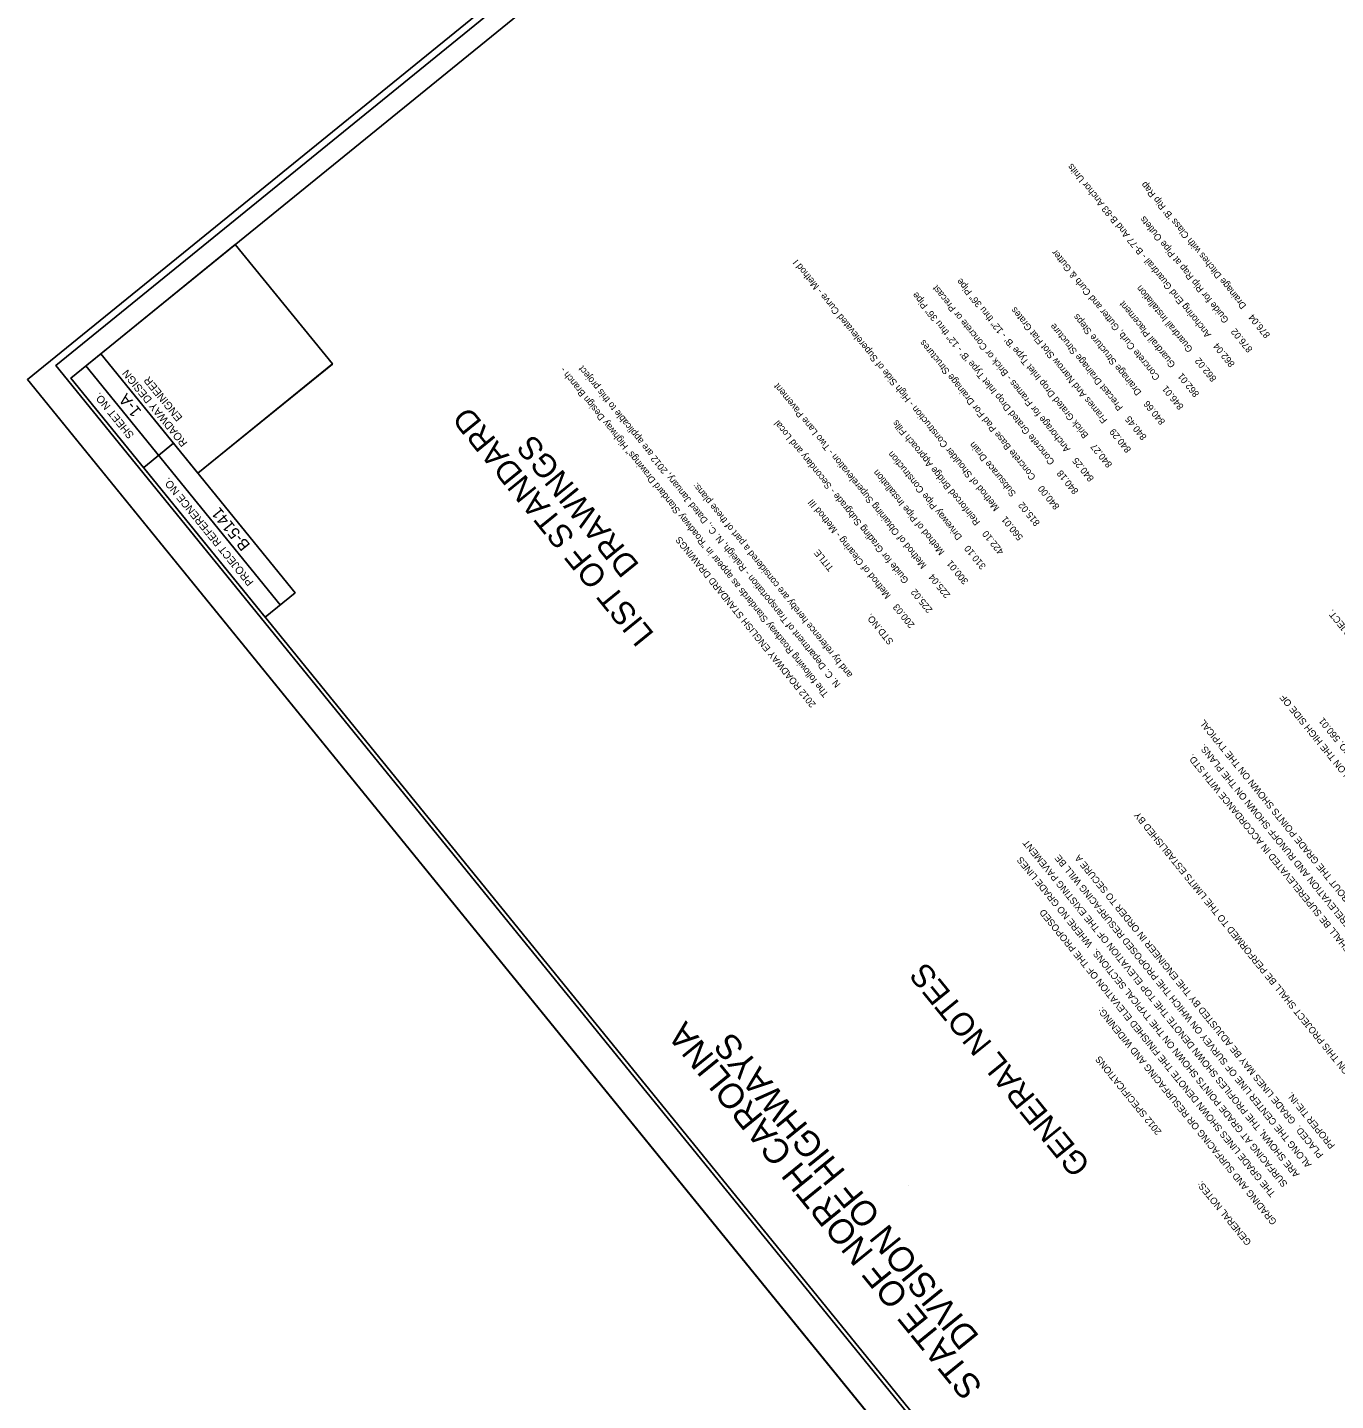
# Model space of a CAD drawing. Extents: x 2596486 to 2602076, y 851390 to 856110.
# Drawn here: x 2600164 to 2601014, y 853035 to 853927 of the extents above; entities that cross this region are included whole.
import ezdxf

# ---------------------------------------------------------------- set-up
doc = ezdxf.new("R2010")
doc.units = 0
for name, color, linetype in [('Sheet Cutting Line CELL', 7, 'Continuous'), ('Sheet Data Field CELL', 7, 'Continuous'), ('Sheet Data Text CELL', 7, 'Continuous'), ('Sheet Plan CELL', 7, 'Continuous'), ('Sheet Plot Border Inside CELL', 7, 'Continuous'), ('Sheet Plot Border Outside CELL', 7, 'Continuous'), ('Sheet Summary CELL', 7, 'Continuous')]:
    doc.layers.add(name, color=color, linetype=linetype)

msp = doc.modelspace()

# ---------------------------------------------------------------- linework, layer by layer
at = {"layer": 'Sheet Cutting Line CELL'}
msp.add_line((2600164.17, 853698.55), (2601225.98, 852392.13), dxfattribs=at)
at = {"layer": 'Sheet Plan CELL'}
for p, q in [((2600337.97, 853560.11), (2600211.8, 853715.35)), ((2600337.97, 853560.11), (2600211.8, 853715.35)), ((2600328.27, 853552.22), (2600202.1, 853707.46)), ((2600274.87, 853637.75), (2600362.13, 853708.67)), ((2600239.7, 853641.38), (2600259.1, 853657.15))]:
    msp.add_line(p, q, dxfattribs=at)
for points in [[(2600192.36, 853699.55), (2601138.43, 852535.53), (2601953.24, 853197.77), (2601007.17, 854361.8)], [(2600274.87, 853637.75), (2600211.8, 853715.35), (2600299.1, 853786.3), (2600362.17, 853708.7)], [(2600318.53, 853544.31), (2600192.36, 853699.55), (2600211.8, 853715.35), (2600337.97, 853560.11)]]:
    msp.add_lwpolyline(points, close=True, dxfattribs=at)
at = {"layer": 'Sheet Plot Border Inside CELL'}
msp.add_lwpolyline([(2602052, 853080.23), (2601001.23, 854373.07), (2600182.53, 853707.67), (2601233.3, 852414.83)], close=True, dxfattribs=at)
at = {"layer": 'Sheet Plot Border Outside CELL'}
msp.add_lwpolyline([(2602075.72, 853082.76), (2601013.91, 854389.18), (2600164.17, 853698.55), (2601225.98, 852392.13)], close=True, dxfattribs=at)
at = {"layer": 'Sheet Summary CELL'}
msp.add_line((2600736.18, 853175.2), (2600736.18, 853175.2), dxfattribs=at)
msp.add_line((2600736.18, 853175.2), (2600736.18, 853175.2), dxfattribs=at)

# ---------------------------------------------------------------- texts
at = {"layer": 'Sheet Data Field CELL'}
for s, p in [('1-A', (2600238.53, 853678.02)), ('B-5141   ', (2600309.2, 853591.15))]:
    msp.add_text(s, height=7.5, rotation=129.10281, dxfattribs=at).set_placement(p)
at = {"layer": 'Sheet Data Text CELL'}
for s, height, rotation, p in [('862.04    Anchoring End Guardrail - B-77 And B-83 Anchor Units', 4.4, 129.10281, (2600948.42, 853708.82)), ("876.04    Drainage Ditches with Class 'B' Rip Rap", 4.4, 129.10281, (2600971.36, 853727.56)), ('876.02    Guide for Rip Rap at Pipe Outlets', 4.4, 129.10281, (2600959.98, 853718.31)), ('846.01    Concrete Curb, Gutter and Curb & Gutter', 4.4, 129.10281, (2600915.22, 853681.12)), ('560.01    Method of Shoulder Construction - High Side of Superelevated Curve - Method I', 4.4, 129.10281, (2600810.92, 853596.24)), ('840.27    Brick Grated Drop Inlet Type \'B\' - 12" thru 36" Pipe', 4.4, 129.10281, (2600868.82, 853643.51)), ('840.18    Concrete Grated Drop Inlet Type \'B\' - 12" thru 36" Pipe', 4.4, 129.10281, (2600846.89, 853626.21)), ('840.25    Anchorage for Frames - Brick or Concrete or Precast', 4.4, 129.10281, (2600857, 853634.43)), ('862.02    Guardrail Installation', 4.4, 129.10281, (2600936.59, 853699.31)), ('840.29    Frames And Narrow Slot Flat Grates', 4.4, 129.10281, (2600881.1, 853653.22)), ('862.01    Guardrail Placement', 4.4, 129.10281, (2600925.32, 853689.33)), ('840.66    Drainage Structure Steps', 4.4, 129.10281, (2600903.21, 853671.35)), ('840.45    Precast Drainage Structure', 4.4, 129.10281, (2600891.22, 853661.44)), ('840.00    Concrete Base Pad For Drainage Structures', 4.4, 129.10281, (2600834.62, 853616.23)), ('The following Roadway Standards as appear in "Roadway Standard Drawings" Highway Design Branch -', 4.4, 128.94401, (2600684.6, 853494.37)), ('N. C. Department of Transportation - Raleigh, N. C., Dated January, 2012 are applicable to this project', 4.4, 128.94401, (2600692.37, 853500.66)), ('225.04    Method of Obtaining Superelevation - Two Lane Pavement', 4.4, 129.10281, (2600763.67, 853558.8)), ('LIST OF STANDARD', 15, 129.10272, (2600571.6, 853533.28)), ('225.02    Guide for Grading Subgrade - Secondary and Local', 4.4, 129.10281, (2600752.13, 853549.11)), ('422.10    Reinforced Bridge Approach Fills', 4.4, 129.10281, (2600798.47, 853586.93)), ('DRAWINGS', 15, 129.10272, (2600562, 853578.08)), ('815.02    Subsurace Drain', 4.4, 129.10281, (2600821.83, 853605.57)), ('310.10    Driveway Pipe Construction', 4.4, 129.10281, (2600786.79, 853577.39)), ('300.01    Method of Pipe Installation ', 4.4, 129.10281, (2600775.38, 853567.68)), ('and by reference hereby are considered a part of these plans:', 4.4, 128.94401, (2600700.15, 853506.94)), ('200.03    Method of Clearing - Method III', 4.4, 129.10281, (2600740.49, 853539.31)), ('2012 ROADWAY ENGLISH STANDARD DRAWINGS', 4.4, 128.94401, (2600676.31, 853487.68)), ('STD.NO.                       TITLE', 4.4, 129.10281, (2600726.78, 853528.47)), ('         SUITABLE CONNECTIONS WITH ALL ROADS, STREETS, AND DRIVES ENTERING THIS PROJECT.  ', 4.4, 129.10281, (2601192.55, 853326.9)), ('         ASPHALT, EARTH, AND CONCRETE SHOULDER CONSTRUCTION ON THE HIGH SIDE OF', 4.4, 129.10281, (2601146.75, 853289.88)), ('         SUPERELEVATION IS TO BE REVOLVED ABOUT THE GRADE POINTS SHOWN ON THE TYPICAL', 4.4, 129.10281, (2601107.18, 853257.9)), ('         SUPERELEVATED CURVES SHALL BE IN ACCORDANCE WITH STD. NO. 560.01', 4.4, 129.10281, (2601154.5, 853296.14)), ('         NO. 225.04 USING THE RATE OF SUPERELEVATION AND RUNOFF SHOWN ON THE PLANS.', 4.4, 129.10281, (2601099.39, 853251.61)), ('         ALL CURVES ON THIS PROJECT SHALL BE SUPERELEVATED IN ACCORDANCE WITH STD.', 4.4, 129.10281, (2601091.61, 853245.32)), ('         CLEARING ON THIS PROJECT SHALL BE PERFORMED TO THE LIMITS ESTABLISHED BY ', 4.4, 129.10281, (2601052.12, 853213.41)), ('         ARE SHOWN, THE PROFILES SHOWN DENOTE THE TOP ELEVATION OF THE EXISTING PAVEMENT ', 4.4, 129.10281, (2600999.69, 853171.04)), ('         SURFACING AT GRADE POINTS SHOWN ON THE TYPICAL SECTIONS.  WHERE NO GRADE LINES ', 4.4, 129.10281, (2600991.91, 853164.75)), ('         ALONG THE CENTER LINE OF SURVEY ON WHICH THE PROPOSED RESURFACING WILL BE ', 4.4, 129.10281, (2601007.44, 853177.3)), ('         PLACED.  GRADE LINES MAY BE ADJUSTED BY THE ENGINEER IN ORDER TO SECURE A ', 4.4, 129.10281, (2601015.22, 853183.59)), ('         THE GRADE LINES SHOWN DENOTE THE FINISHED ELEVATION OF THE PROPOSED ', 4.4, 129.10281, (2600984.08, 853158.42)), ('GENERAL NOTES', 15, 129.10272, (2600855.04, 853188.57)), ('GRADING AND SURFACING OR RESURFACING AND WIDENING:  ', 4.4, 129.10281, (2600975.68, 853151.63)), ('GENERAL NOTES:                         2012 SPECIFICATIONS', 4.4, 129.10281, (2600959.15, 853138.27)), ('         PROPER TIE-IN.  ', 4.4, 129.10281, (2601022.73, 853189.65))]:
    msp.add_text(s, height=height, rotation=rotation, dxfattribs=at).set_placement(p)
at = {"layer": 'Sheet Plan CELL'}
for s, height, p in [('ROADWAY DESIGN', 5.0001, (2600268.3, 853657.41)), ('ENGINEER', 5, (2600265.1, 853673.94)), ('SHEET NO.', 5, (2600233.69, 853662.65)), ('PROJECT REFERENCE NO.', 5.0001, (2600311.28, 853567.02))]:
    msp.add_text(s, height=height, rotation=129.10281, dxfattribs=at).set_placement(p)
at = {"layer": 'Sheet Summary CELL'}
for s, p in [('STATE OF NORTH CAROLINA', (2600784.99, 853044.51)), ('STATE OF NORTH CAROLINA', (2600784.99, 853044.51)), ('DIVISION OF HIGHWAYS', (2600782.76, 853076.98)), ('DIVISION OF HIGHWAYS', (2600782.76, 853076.98))]:
    msp.add_text(s, height=16.2501, rotation=129.10281, dxfattribs=at).set_placement(p)

doc.saveas('drawing.dxf')
